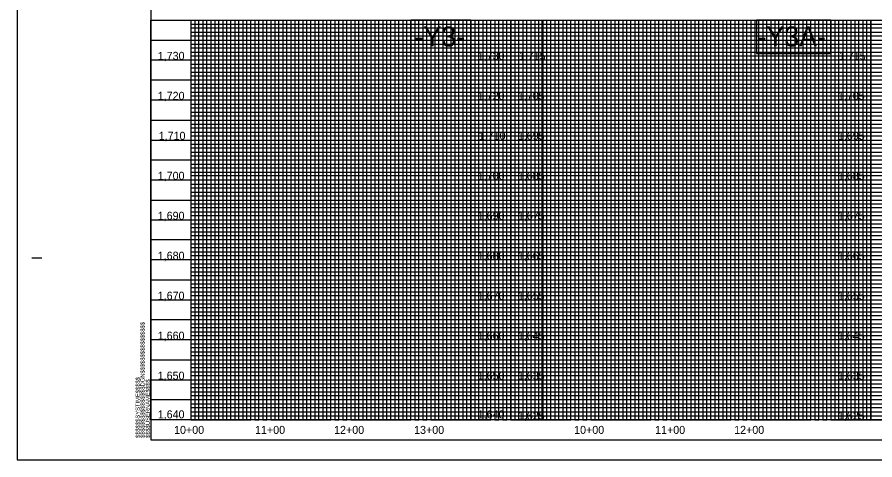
# Model space of a CAD drawing. Extents: x 505602 to 507705, y 483109 to 484209.
# Drawn here: x 505602 to 506674, y 483109 to 483662 of the extents above; entities that cross this region are included whole.
import ezdxf

# ---------------------------------------------------------------- set-up
doc = ezdxf.new("R2010")
doc.units = 0
for name, color, linetype in [('Exist Vertical Profile Vertical Axis Label', 7, 'Continuous'), ('Old_Level_1', 7, 'Continuous'), ('Prop Grid Mask', 7, 'Continuous'), ('Sheet Layout Profile Border Port 2', 7, 'Continuous'), ('Sheet Plot Border Outside CELL', 7, 'Continuous'), ('Sheet Profile CELL', 7, 'Continuous'), ('Sheet Profile Grid Major CELL', 7, 'Continuous'), ('Sheet Profile Grid Middle CELL', 7, 'Continuous'), ('Sheet Profile Grid Minor CELL', 7, 'Continuous')]:
    doc.layers.add(name, color=color, linetype=linetype)

msp = doc.modelspace()

# ---------------------------------------------------------------- linework, layer by layer
at = {"layer": 'Prop Grid Mask'}
for points in [[(506169.1, 483658.7), (506094.1, 483658.7), (506094.1, 483618.7), (506169.1, 483618.7)], [(506619.1, 483658.7), (506526.1, 483658.7), (506526.1, 483617), (506619.1, 483617)]]:
    msp.add_lwpolyline(points, close=True, dxfattribs=at)
at = {"layer": 'Sheet Layout Profile Border Port 2'}
for points in [[(505769.1, 483658.7), (506169.1, 483658.7), (506169.1, 483158.7), (505769.1, 483158.7)], [(506169.1, 483658.7), (507219.1, 483658.7), (507219.1, 483158.7), (506169.1, 483158.7)], [(506258.1, 483658.7), (506669.1, 483658.7), (506669.1, 483158.7), (506258.1, 483158.7)]]:
    msp.add_lwpolyline(points, close=True, dxfattribs=at)
at = {"layer": 'Sheet Plot Border Outside CELL'}
msp.add_lwpolyline([(505602.1, 483108.7), (507286.1, 483108.7), (507286.1, 484208.7), (505602.1, 484208.7)], close=True, dxfattribs=at)
at = {"layer": 'Sheet Profile CELL'}
for p, q in [((505769.1, 483658.7), (507269.1, 483658.7)), ((506219.1, 483158.7), (506219.1, 483658.7)), ((506669.1, 483158.7), (506669.1, 483658.7)), ((505620.6, 483361.2), (505633.1, 483361.2)), ((507269.1, 483158.7), (505769.1, 483158.7)), ((505769.1, 483133.7), (507269.1, 483133.7)), ((505769.1, 483133.7), (505769.1, 483133.7)), ((505769.1, 483133.7), (505769.1, 483133.7)), ((505769.1, 483133.7), (505769.1, 483133.7)), ((505769.1, 483133.7), (505769.1, 483133.7)), ((505769.1, 483133.7), (505769.1, 483133.7)), ((505769.1, 483133.7), (505769.1, 483133.7)), ((505769.1, 483133.7), (505769.1, 483133.7))]:
    msp.add_line(p, q, dxfattribs=at)
msp.add_lwpolyline([(507269.1, 484183.7), (505769.1, 484183.7), (505769.1, 483133.7), (507269.1, 483133.7)], close=True, dxfattribs=at)
msp.add_lwpolyline([(505806.6, 483133.7), (505806.6, 483133.7)], dxfattribs=at)
at = {"layer": 'Sheet Profile Grid Major CELL'}
for p, q in [((506269.1, 483658.7), (506319.1, 483658.7)), ((506369.1, 483658.7), (506419.1, 483658.7)), ((506469.1, 483658.7), (506519.1, 483658.7))]:
    msp.add_line(p, q, dxfattribs=at)
for points in [[(505819.1, 483658.7), (505819.1, 483158.7), (505869.1, 483158.7), (505869.1, 483658.7), (505919.1, 483658.7), (505919.1, 483158.7), (505969.1, 483158.7), (505969.1, 483658.7), (506019.1, 483658.7), (506019.1, 483158.7), (506069.1, 483158.7), (506069.1, 483658.7), (506119.1, 483658.7), (506119.1, 483158.7), (506169.1, 483158.7), (506169.1, 483658.7), (506219.1, 483658.7), (506219.1, 483158.7), (506269.1, 483158.7), (506269.1, 483658.7), (506319.1, 483658.7), (506319.1, 483158.7), (506369.1, 483158.7), (506369.1, 483658.7), (506419.1, 483658.7), (506419.1, 483158.7), (506469.1, 483158.7), (506469.1, 483658.7), (506519.1, 483658.7), (506519.1, 483158.7), (506569.1, 483158.7), (506569.1, 483658.7), (506619.1, 483658.7), (506619.1, 483158.7), (506669.1, 483158.7), (506669.1, 483658.7), (506719.1, 483658.7)], [(507269.1, 483608.7), (505769.1, 483608.7)], [(507269.1, 483558.7), (505769.1, 483558.7), (505769.1, 483508.7), (507269.1, 483508.7)], [(507269.1, 483458.7), (505769.1, 483458.7), (505769.1, 483408.7), (507269.1, 483408.7)], [(507269.1, 483358.7), (505769.1, 483358.7), (505769.1, 483308.7), (507269.1, 483308.7)], [(507269.1, 483258.7), (505769.1, 483258.7), (505769.1, 483258.7), (505769.1, 483208.7), (507269.1, 483208.7)], [(507269.1, 483158.7), (505769.1, 483158.7)]]:
    msp.add_lwpolyline(points, dxfattribs=at)
at = {"layer": 'Sheet Profile Grid Middle CELL'}
for points in [[(505794.1, 483658.7), (505844.1, 483658.7), (505844.1, 483158.7), (505894.1, 483158.7), (505894.1, 483658.7), (505944.1, 483658.7), (505944.1, 483158.7), (505994.1, 483158.7), (505994.1, 483658.7), (506044.1, 483658.7), (506044.1, 483158.7), (506094.1, 483158.7), (506094.1, 483658.7), (506144.1, 483658.7), (506144.1, 483158.7), (506194.1, 483158.7), (506194.1, 483658.7), (506244.1, 483658.7), (506244.1, 483158.7), (506294.1, 483158.7), (506294.1, 483658.7), (506344.1, 483658.7), (506344.1, 483158.7), (506394.1, 483158.7), (506394.1, 483158.7), (506394.1, 483658.7), (506444.1, 483658.7), (506444.1, 483158.7), (506494.1, 483158.7), (506494.1, 483658.7), (506544.1, 483658.7), (506544.1, 483158.7), (506594.1, 483158.7), (506594.1, 483658.7), (506644.1, 483658.7), (506644.1, 483158.7), (506694.1, 483158.7)], [(505769.1, 483633.7), (507269.1, 483633.7)], [(507269.1, 483583.7), (505769.1, 483583.7), (505769.1, 483533.7), (507269.1, 483533.7)], [(507269.1, 483483.7), (505769.1, 483483.7), (505769.1, 483433.7), (507269.1, 483433.7)], [(507269.1, 483383.7), (505769.1, 483383.7), (505769.1, 483333.7), (507269.1, 483333.7)], [(507269.1, 483283.7), (505769.1, 483283.7), (505769.1, 483233.7), (507269.1, 483233.7)], [(507269.1, 483183.7), (505769.1, 483183.7)]]:
    msp.add_lwpolyline(points, dxfattribs=at)
at = {"layer": 'Sheet Profile Grid Minor CELL'}
for p, q in [((505819.1, 483653.7), (507219.1, 483653.7)), ((507219.1, 483648.7), (505819.1, 483648.7)), ((505819.1, 483643.7), (507219.1, 483643.7)), ((507219.1, 483638.7), (505819.1, 483638.7)), ((505819.1, 483628.7), (507219.1, 483628.7)), ((507219.1, 483623.7), (505819.1, 483623.7)), ((505819.1, 483618.7), (507219.1, 483618.7)), ((507219.1, 483613.7), (505819.1, 483613.7)), ((505819.1, 483603.7), (507219.1, 483603.7)), ((507219.1, 483598.7), (505819.1, 483598.7)), ((505819.1, 483593.7), (507219.1, 483593.7)), ((507219.1, 483588.7), (505819.1, 483588.7)), ((505819.1, 483578.7), (507219.1, 483578.7)), ((507219.1, 483573.7), (505819.1, 483573.7)), ((505819.1, 483568.7), (507219.1, 483568.7)), ((507219.1, 483563.7), (505819.1, 483563.7)), ((505819.1, 483553.7), (507219.1, 483553.7)), ((507219.1, 483548.7), (505819.1, 483548.7)), ((505819.1, 483543.7), (507219.1, 483543.7)), ((507219.1, 483538.7), (505819.1, 483538.7)), ((505819.1, 483528.7), (507219.1, 483528.7)), ((507219.1, 483523.7), (505819.1, 483523.7)), ((505819.1, 483518.7), (507219.1, 483518.7)), ((507219.1, 483513.7), (505819.1, 483513.7)), ((505819.1, 483503.7), (507219.1, 483503.7)), ((507219.1, 483498.7), (505819.1, 483498.7)), ((505819.1, 483493.7), (507219.1, 483493.7)), ((507219.1, 483488.7), (505819.1, 483488.7)), ((505819.1, 483478.7), (507219.1, 483478.7)), ((507219.1, 483473.7), (505819.1, 483473.7)), ((505819.1, 483468.7), (507219.1, 483468.7)), ((507219.1, 483463.7), (505819.1, 483463.9)), ((505819.1, 483453.7), (507219.1, 483453.7)), ((507219.1, 483448.7), (505819.1, 483448.7)), ((505819.1, 483443.7), (507219.1, 483443.7)), ((507219.1, 483438.7), (505819.1, 483438.7)), ((505819.1, 483428.7), (507219.1, 483428.7)), ((507219.1, 483423.7), (505819.1, 483423.7)), ((505819.1, 483418.7), (507219.1, 483418.7)), ((507219.1, 483413.7), (505819.1, 483413.7)), ((505819.1, 483403.7), (507219.1, 483403.7)), ((507219.1, 483398.7), (505819.1, 483398.7)), ((505819.1, 483393.7), (507219.1, 483393.7)), ((507219.1, 483388.7), (505819.1, 483388.7)), ((505819.1, 483378.7), (507219.1, 483378.7)), ((507219.1, 483373.7), (505819.1, 483373.7)), ((505819.1, 483368.7), (507219.1, 483368.7)), ((507219.1, 483363.7), (505819.1, 483363.7)), ((505819.1, 483353.7), (507219.1, 483353.7)), ((507219.1, 483348.7), (505819.1, 483348.7)), ((505819.1, 483343.7), (507219.1, 483343.7)), ((507219.1, 483338.7), (505819.1, 483338.7)), ((505819.1, 483328.7), (507219.1, 483328.7)), ((507219.1, 483323.7), (505819.1, 483323.7)), ((505819.1, 483318.7), (507219.1, 483318.7)), ((507219.1, 483313.7), (505819.1, 483313.7)), ((505819.1, 483303.7), (507219.1, 483303.7)), ((507219.1, 483298.7), (505819.1, 483298.7)), ((505819.1, 483293.7), (507219.1, 483293.7)), ((507219.1, 483288.7), (505819.1, 483288.7)), ((505819.1, 483278.7), (507219.1, 483278.7)), ((507219.1, 483273.7), (505819.1, 483273.7)), ((505819.1, 483268.7), (507219.1, 483268.7)), ((507219.1, 483263.7), (505819.1, 483263.7)), ((505819.1, 483253.7), (507219.1, 483253.7)), ((507219.1, 483248.7), (505819.1, 483248.7)), ((505819.1, 483243.7), (507219.1, 483243.7)), ((507219.1, 483238.7), (505819.1, 483238.7)), ((505819.1, 483228.7), (507219.1, 483228.7)), ((507219.1, 483223.7), (505819.1, 483223.7)), ((505819.1, 483218.7), (507219.1, 483218.7)), ((507219.1, 483213.7), (505819.1, 483213.7)), ((505819.1, 483203.7), (507219.1, 483203.7)), ((507219.1, 483198.7), (505819.1, 483198.7)), ((505819.1, 483193.7), (507219.1, 483193.7)), ((507219.1, 483188.7), (505819.1, 483188.7)), ((505819.1, 483178.7), (507219.1, 483178.7)), ((507219.1, 483173.7), (505819.1, 483173.7)), ((505819.1, 483168.7), (507219.1, 483168.7)), ((505819.1, 483163.7), (507219.1, 483163.7))]:
    msp.add_line(p, q, dxfattribs=at)
for points in [[(505819.1, 483658.7), (505824.1, 483658.7), (505824.1, 483158.7), (505829.1, 483158.7), (505829.1, 483658.7), (505834.1, 483658.7), (505834.1, 483158.7), (505839.1, 483158.7), (505839.1, 483658.7), (505849.1, 483658.7), (505849.1, 483158.7), (505854.1, 483158.7), (505854.1, 483658.7), (505859.1, 483658.7), (505859.1, 483158.7), (505864.1, 483158.7), (505874.1, 483158.7), (505879.1, 483158.7), (505879.1, 483658.7), (505884.1, 483658.7), (505884.1, 483158.7), (505889.1, 483158.7), (505889.1, 483658.7), (505899.1, 483658.7), (505899.1, 483158.7), (505904.1, 483158.7), (505904.1, 483658.7), (505909.1, 483658.7), (505909.1, 483158.7), (505914.1, 483158.7), (505914.1, 483658.7), (505924.1, 483658.7), (505924.1, 483158.7), (505929.1, 483158.7), (505929.1, 483658.7), (505934.1, 483658.7), (505934.1, 483158.7), (505939.1, 483158.7), (505939.1, 483658.7), (505949.1, 483658.7), (505949.1, 483158.7), (505954.1, 483158.7), (505954.1, 483658.7), (505959.1, 483658.7), (505959.1, 483158.7), (505964.1, 483158.7), (505964.1, 483658.7), (505974.1, 483658.7), (505974.1, 483158.7), (505979.1, 483158.7), (505979.1, 483658.7), (505984.1, 483658.7), (505984.1, 483158.7), (505989.1, 483158.7), (505989.1, 483658.7), (505999.1, 483658.7), (505999.1, 483158.7), (506004.1, 483158.7), (506004.1, 483658.7), (506009.1, 483658.7), (506009.1, 483158.7), (506014.1, 483158.7), (506014.1, 483658.7), (506024.1, 483658.7), (506024.1, 483158.7), (506029.1, 483158.7), (506029.1, 483658.7), (506034.1, 483658.7), (506034.1, 483158.7)], [(505864.1, 483158.7), (505864.1, 483658.7), (505874.1, 483658.7), (505874.1, 483158.7)], [(506034.1, 483158.7), (506039.1, 483158.7), (506039.1, 483658.7), (506049.1, 483658.7), (506049.1, 483158.7), (506054.1, 483158.7), (506054.1, 483658.7), (506059.1, 483658.7), (506059.1, 483158.7), (506064.1, 483158.7), (506064.1, 483658.7), (506074.1, 483658.7), (506074.1, 483158.7), (506079.1, 483158.7), (506079.1, 483658.7), (506084.1, 483658.7), (506084.1, 483158.7), (506089.1, 483158.7), (506089.1, 483658.7), (506099.1, 483658.7), (506099.1, 483158.7), (506104.1, 483158.7), (506104.1, 483658.7), (506109.1, 483658.7), (506109.1, 483158.7), (506114.1, 483158.7), (506114.1, 483658.7), (506124.1, 483658.7), (506124.1, 483158.7), (506129.1, 483158.7), (506129.1, 483658.7), (506134.1, 483658.7), (506134.1, 483158.7), (506139.1, 483158.7), (506139.1, 483658.7), (506149.1, 483658.7), (506149.1, 483158.7), (506154.1, 483158.7), (506154.1, 483658.7), (506159.1, 483658.7), (506159.1, 483158.7), (506164.1, 483158.7), (506164.1, 483658.7), (506174.1, 483658.7), (506174.1, 483158.7), (506179.1, 483158.7), (506179.1, 483658.7), (506184.1, 483658.7), (506184.1, 483158.7), (506189.1, 483158.7), (506189.1, 483658.7), (506199.1, 483658.7), (506199.1, 483158.7), (506204.1, 483158.7), (506204.1, 483658.7), (506209.1, 483658.7), (506209.1, 483158.7), (506214.1, 483158.7), (506214.1, 483658.7), (506224.1, 483658.7), (506224.1, 483158.7), (506229.1, 483158.7), (506229.1, 483658.7), (506234.1, 483658.7), (506234.1, 483158.7), (506239.1, 483158.7), (506239.1, 483658.7), (506249.1, 483658.7), (506249.1, 483158.7), (506254.1, 483158.7), (506254.1, 483658.7), (506259.1, 483658.7), (506259.1, 483158.7), (506264.1, 483158.7), (506264.1, 483658.7), (506274.1, 483658.7), (506274.1, 483158.7), (506279.1, 483158.7), (506279.1, 483658.7), (506284.1, 483658.7), (506284.1, 483158.7), (506289.1, 483158.7), (506289.1, 483658.7), (506299.1, 483658.7), (506299.1, 483158.7), (506304.1, 483158.7), (506304.1, 483658.7), (506309.1, 483658.7), (506309.1, 483158.7), (506314.1, 483158.7), (506314.1, 483658.7), (506324.1, 483658.7), (506324.1, 483158.7), (506329.1, 483158.7), (506329.1, 483658.7), (506334.1, 483658.7), (506334.1, 483158.7), (506339.1, 483158.7), (506339.1, 483658.7), (506349.1, 483658.7)], [(506349.1, 483658.7), (506349.1, 483158.7), (506354.1, 483158.7), (506354.1, 483658.7), (506359.1, 483658.7), (506359.1, 483158.7), (506364.1, 483158.7), (506364.1, 483658.7), (506374.1, 483658.7), (506374.1, 483158.7), (506379.1, 483158.7), (506379.1, 483658.7), (506384.1, 483658.7), (506384.1, 483158.7), (506389.1, 483158.7), (506389.1, 483658.7), (506399.1, 483658.7), (506399.1, 483158.7), (506404.1, 483158.7), (506404.1, 483658.7), (506409.1, 483658.7), (506409.1, 483158.7), (506414.1, 483158.7), (506414.1, 483658.7), (506424.1, 483658.7), (506424.1, 483158.7), (506429.1, 483158.7), (506429.1, 483658.7), (506434.1, 483658.7), (506434.1, 483158.7), (506439.1, 483158.7), (506439.1, 483658.7), (506449.1, 483658.7), (506449.1, 483158.7), (506454.1, 483158.7), (506454.1, 483658.7), (506459.1, 483658.7), (506459.1, 483158.7), (506464.1, 483158.7), (506464.1, 483658.7), (506474.1, 483658.7), (506474.1, 483158.7), (506474.1, 483158.7), (506479.1, 483158.7), (506479.1, 483658.7), (506484.1, 483658.7), (506484.1, 483158.7), (506489.1, 483158.7), (506489.1, 483658.7), (506499.1, 483658.7), (506499.1, 483158.7), (506504.1, 483158.7), (506504.1, 483658.7), (506509.1, 483658.7), (506509.1, 483158.7), (506514.1, 483158.7), (506514.1, 483658.7), (506524.1, 483658.7), (506524.1, 483158.7), (506529.1, 483158.7), (506529.1, 483658.7), (506534.1, 483658.7), (506534.1, 483158.7), (506539.1, 483158.7), (506539.1, 483658.7), (506549.1, 483658.7), (506549.1, 483158.7), (506554.1, 483158.7), (506554.1, 483658.7), (506559.1, 483658.7), (506559.1, 483158.7), (506564.1, 483158.7), (506564.1, 483658.7), (506574.1, 483658.7), (506574.1, 483158.7), (506579.1, 483158.7), (506579.1, 483658.7), (506584.1, 483658.7), (506584.1, 483158.7), (506589.1, 483158.7), (506589.1, 483658.7), (506599.1, 483658.7), (506599.1, 483158.7), (506604.1, 483158.7), (506604.1, 483658.7), (506609.1, 483658.7), (506609.1, 483158.7), (506614.1, 483158.7), (506614.1, 483658.7), (506624.1, 483658.7), (506624.1, 483158.7), (506628.8, 483159.3), (506629.1, 483158.7), (506629.1, 483658.7), (506634.1, 483658.7), (506634.1, 483158.7), (506639.1, 483158.7), (506639.1, 483658.7), (506649.1, 483658.7), (506649.1, 483158.7), (506654.1, 483158.7)], [(506654.1, 483158.7), (506654.1, 483658.7), (506659.1, 483658.7), (506659.1, 483158.7), (506664.1, 483158.7), (506664.1, 483658.7), (506674.1, 483658.7)]]:
    msp.add_lwpolyline(points, dxfattribs=at)

# ---------------------------------------------------------------- texts
at = {"layer": 'Exist Vertical Profile Vertical Axis Label'}
for s, p in [('1,730', (505777.8, 483609)), ('1,730', (506177.8, 483609)), ('1,715', (506229.1, 483609)), ('1,715', (506629.1, 483609)), ('1,720', (505777.8, 483559)), ('1,720', (506177.8, 483559)), ('1,705', (506227.9, 483559)), ('1,705', (506627.9, 483559)), ('1,710', (505779, 483509)), ('1,710', (506179, 483509)), ('1,695', (506227.9, 483509)), ('1,695', (506627.9, 483509)), ('1,700', (505777.8, 483459)), ('1,700', (506177.8, 483459)), ('1,685', (506227.9, 483459)), ('1,685', (506627.9, 483459)), ('1,690', (505777.8, 483409)), ('1,690', (506177.8, 483409)), ('1,675', (506227.9, 483409)), ('1,675', (506627.9, 483409)), ('1,680', (505777.8, 483359)), ('1,680', (506177.8, 483359)), ('1,665', (506227.9, 483359)), ('1,665', (506627.9, 483359)), ('1,665', (506627.9, 483359)), ('1,670', (505777.8, 483309)), ('1,670', (506177.8, 483309)), ('1,655', (506227.9, 483309)), ('1,655', (506627.9, 483309)), ('1,655', (506627.9, 483309)), ('1,660', (505777.8, 483259)), ('1,660', (506177.8, 483259)), ('1,645', (506227.9, 483259)), ('1,645', (506627.9, 483259)), ('1,645', (506627.9, 483259)), ('1,650', (505777.8, 483209)), ('1,650', (506177.8, 483209)), ('1,635', (506227.9, 483209)), ('1,635', (506627.9, 483209)), ('1,635', (506627.9, 483209)), ('1,640', (505777.8, 483160.6)), ('1,640', (506177.8, 483160.6)), ('1,625', (506227.9, 483159)), ('1,625', (506627.9, 483159)), ('1,625', (506627.9, 483159)), ('10+00', (505798.2, 483141.2)), ('11+00', (505899.4, 483141.2)), ('12+00', (505998.2, 483141.2)), ('13+00', (506098.2, 483141.2)), ('10+00', (506298.2, 483141.2)), ('11+00', (506399.4, 483141.2)), ('12+00', (506498.2, 483141.2))]:
    msp.add_text(s, height=10, dxfattribs=at).set_placement(p)
at = {"layer": 'Old_Level_1'}
for s, p in [('-Y3-', (506098.8, 483625.7)), ('-Y3A-', (506527.4, 483625.7))]:
    msp.add_text(s, height=25, dxfattribs=at).set_placement(p)
at = {"layer": 'Sheet Profile CELL'}
for s, p in [('$$$$$$$$$$$$$$$$DGN$$$$$$$$$$$$$$$$', (505761.4, 483136.1)), ('$$$$$$SYSTIME$$$$$', (505755.4, 483136.1)), ('$$$$USERNAME$$$$', (505768, 483136.1))]:
    msp.add_text(s, height=5.25, rotation=90, dxfattribs=at).set_placement(p)

doc.saveas('drawing.dxf')
